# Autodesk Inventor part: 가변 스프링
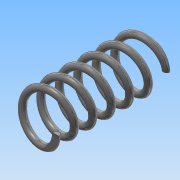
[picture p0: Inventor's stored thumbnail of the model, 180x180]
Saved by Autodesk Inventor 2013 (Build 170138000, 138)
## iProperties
Created: 2015-05
Part Number: 가변 스프링
Material: 강철, 탄소
Document SubType Name: Modeling
Designer: Administrator
Density: 7.87 g/cm^3
Mass: 11.4963 g
Surface Area: 23.7324 cm^2
Volume: 1.46077 cm^3
Author: Administrator
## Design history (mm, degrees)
sketch "스케치1"
  geometry: L1 (0, 0)-(0, 42); L2 (0, 42)-(8, 42); L3 (0, 0)-(8, 0); C1 r 1.25 at (8, 0)
  constraints: 6 end point, 1 centre point, 1 coincident, 1 parallel, 1 perpendicular, 1 vertical
  dimensions: "d0" = 42 distance of L1.start L1.end (derived); "d1" = 8 distance of L1.end L2.end; "d2" = 8 distance of L1.start L3.end; "d3" = 2.5 diameter of C1
feature "코일1" sketch "스케치1" pitch "d4" = 10; turns "d6" = 6; dims "d5" = 42 (= d0), "d7" = 0, angle "d8" = 90 deg, angle "d9" = 90 deg, "d10" = 0, "d11" = 0
sketch "스케치2"
  geometry: L1 (42, 16.451)-(0, 16.451); L2 (0, 16.451)-(0, -16.593); L3 (0, -16.593)-(42, -16.593); L4 (42, -16.593)-(42, 16.451); 1 further point
  constraints: 8 end point, 2 parallel, 1 horizontal, 1 perpendicular, 1 point on line
  dimensions: "d12" = 42 distance of L1.start L1.end (derived); "d14" = 16.45074 distance of point (0, 0) L1.end; "d15" = 16.59256 distance from line of L3 point (0, 0)
extrude "돌출1" sketch "스케치2" stored distance "d16" = 10; taper "d17" = 0 deg
node "솔리드1"
